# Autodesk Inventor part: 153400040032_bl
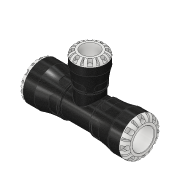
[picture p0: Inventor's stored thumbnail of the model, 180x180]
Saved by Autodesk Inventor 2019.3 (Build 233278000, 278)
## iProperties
Created: 2016-12
Part Number: 153400040032_bl
Material: PVC-Piping
Description: PLASSON G-PLASS  REDUCING TEE 40X32X40
Document SubType Name: Modeling
Designer: KIM
Mass: 664.223 g
Surface Area: 733.008 cm^2
Volume: 474.445 cm^3
Density: 1.4 g/cm^3
Appearance: Black Cast
Author: KIM
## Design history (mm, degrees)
derived "153400.ipt"
feature "Solid1::153400.ipt" dims "ScaleForDerivedMember" = 10
tag "TaggingFeature1"
body "Solid1"
other parameters: "l_" = 73 [user parameter], "A_" = 95 [user parameter], "H_" = 198 [user parameter], "d_1" = 32 [user parameter], "E_1" = 58 [user parameter], "l_1" = 56 [user parameter], "d230" = 58 [user parameter], "d232" = 9 [user parameter], "d1" = 30.66 [user parameter], "d8" = 59.5 [user parameter], "d13" = 8 [user parameter], "d14" = 8 [user parameter], "d15" = 0 [user parameter], "d17" = 360 deg [user parameter], "d19" = 8 deg [user parameter], "d20" = 0.8 [user parameter], "d21" = 0.8 [user parameter], "d22" = 8 deg [user parameter], "d24" = 0 [user parameter], "d26" = 360 deg [user parameter], "d33" = 7 [user parameter], "d43" = 54.6 [user parameter], "d51" = 0.7 [user parameter], "d54" = 14 [user parameter], "d55" = 8.8 [user parameter], "d57" = 15.68 [user parameter], "d58" = 0 [user parameter], "d74" = 0 [user parameter], "d77" = 3.33333 [user parameter], "d78" = 73 [user parameter], "d79" = 54.6 [user parameter], "d80" = 198 [user parameter], "d82" = 0.8 [user parameter], "d115" = 360 deg [user parameter], "d139" = 8 [user parameter], "d140" = 0 [user parameter], "d142" = 360 deg [user parameter], "d207" = 90 deg [user parameter], "d209" = 23.52 [user parameter], "d210" = 32 [user parameter], "d212" = 58 [user parameter], "d213" = 49.3 [user parameter], "d215" = 45.24 [user parameter], "d216" = 2.66667 [user parameter], "d217" = 56 [user parameter], "d225" = 95 [user parameter], "d226" = 56 [user parameter], "d228" = 11.9 [user parameter], "d229" = 7.2 [user parameter], "d233" = 7.2 [user parameter], "d234" = 0 [user parameter], "d236" = 360 deg [user parameter], "d238" = 8 deg [user parameter], "d239" = 8 deg [user parameter], "d240" = 0.8 [user parameter], "d241" = 0.8 [user parameter], "d243" = 0 [user parameter], "d245" = 360 deg [user parameter], "d247" = 1.4 [user parameter], "d248" = 4.38 [user parameter], "d249" = 3.36 [user parameter], "d250" = 9.52 [user parameter], "d252" = 11.2 [user parameter], "d253" = 7.36 [user parameter], "d254" = 15.68 [user parameter], "d255" = 0 [user parameter], "d257" = 360 deg [user parameter], "d259" = 0.8 [user parameter], "d261" = 0 [user parameter], "d262" = 1.4 [user parameter], "d264" = 0 [user parameter], "d266" = 0 [user parameter], "d267" = 0.7 [user parameter]
